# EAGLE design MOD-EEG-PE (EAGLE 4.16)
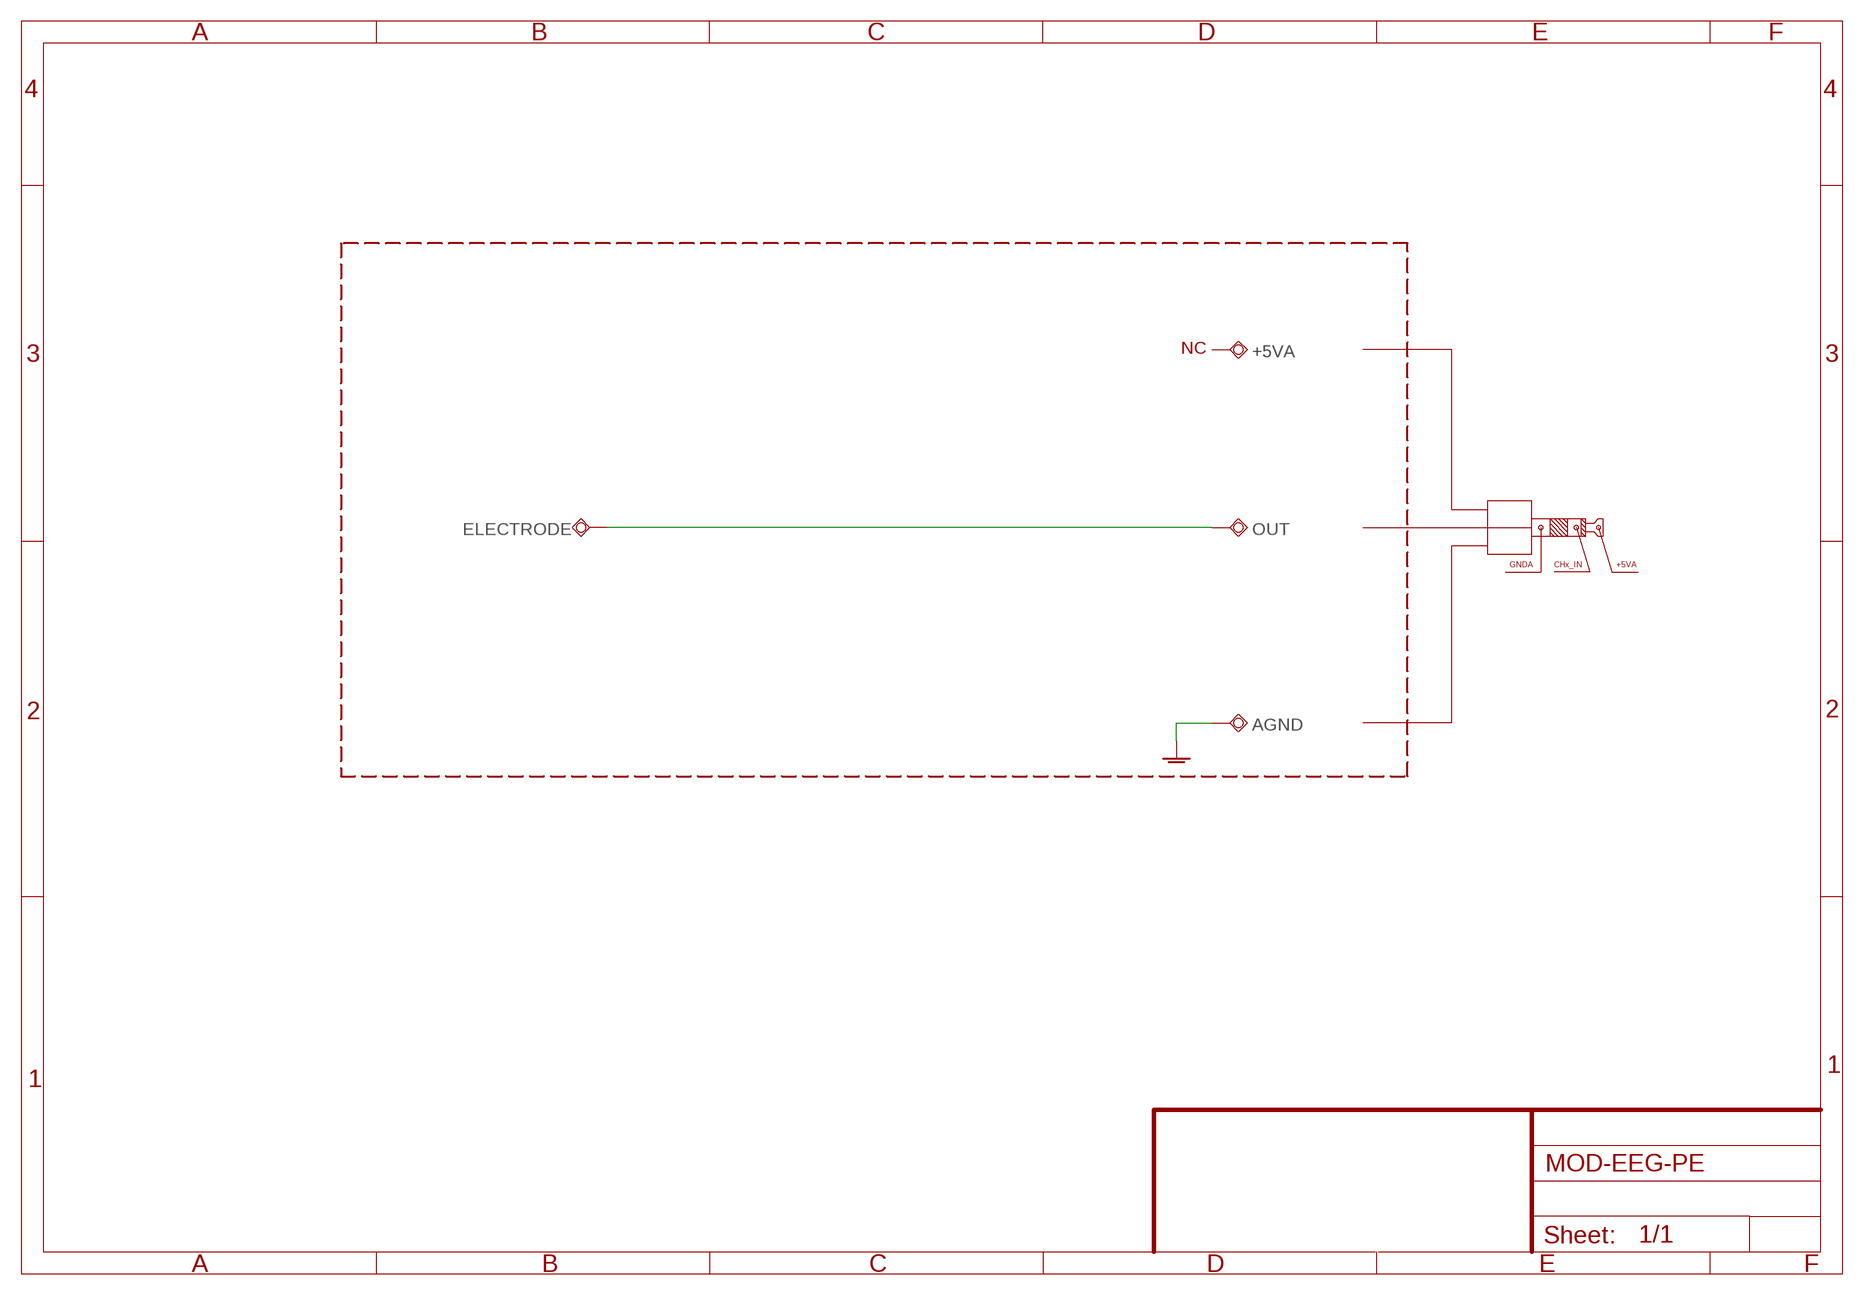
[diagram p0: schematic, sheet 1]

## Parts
+5VA  TESTPAD80/50  [SMD80/50]
AGND  TESTPAD80/50  [SMD80/50]
ELECTRODE  TESTPAD80/50  [SMD80/50]
OUT  TESTPAD80/50  [SMD80/50]

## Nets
ELECTRODE: ELECTRODE.P$1(PP) OUT.P$1(PP)
GNDA: AGND.P$1(PP)
Unconnected: +5VA.P$1(PP)

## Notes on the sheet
- NC
- GNDA | CHx_IN | +5VA

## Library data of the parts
+5VA AGND ELECTRODE OUT = gogo:TESTPAD: drill 40mils, diameter 70mils

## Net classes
1 pwr: width 0.4 mm, drill 0.23 mm

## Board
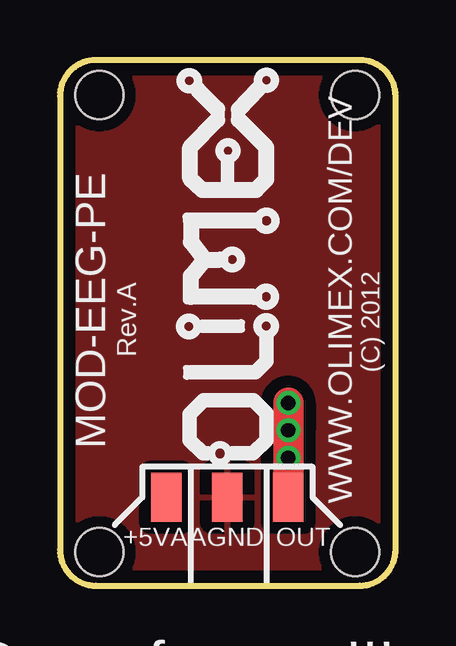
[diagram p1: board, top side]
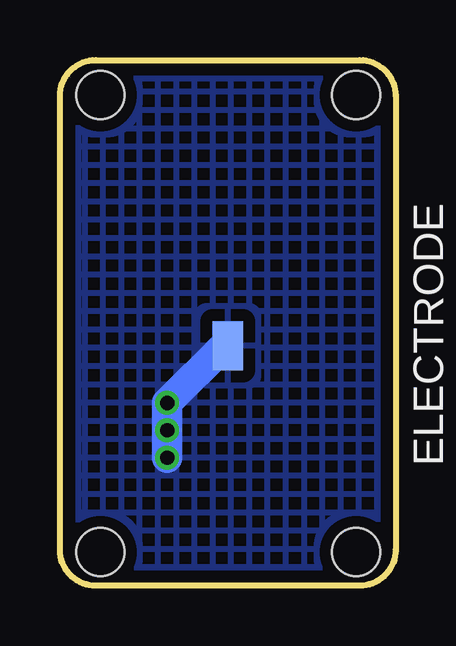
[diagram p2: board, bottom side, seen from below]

Size 14 x 21.91 mm. Coordinates in mm from the lower left corner, seen from the top.
Outline: 12.5,0 arc90 14,1.5 14,20.41 arc90 12.5,21.91 1.5,21.91 arc90 0,20.41 0,1.5 arc90 1.5,0 12.5,0
Copper layers (1+16): Top 0.035mm / dielectric 1.5mm / Bottom 0.035mm
Design rules "default": minimum track width 10mil, minimum drill 0.6mm, track to track 10mil, track to pad 10mil, pad to pad 10mil, via to via 10mil, smd to smd 1mil, copper to edge 10mil, drill to drill 10mil, minimum pad ring 10mil, minimum via ring 8mil, stop-mask expansion 4mil, vias tented up to drill 28mil, thermal gap 20mil
Holes 2 mm at 1.65,1.4 12.32,1.4 1.65,20.45 12.32,20.45

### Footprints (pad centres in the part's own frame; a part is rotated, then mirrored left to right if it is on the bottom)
SMD80/50 = smd 2.032 x 1.27: P$1 0,0

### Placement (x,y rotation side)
+5VA  4.45,3.68 90 top
AGND  6.99,3.68 90 top
ELECTRODE  7,10 270 bottom
OUT  9.53,3.68 90 top
U$1  [OLIMEX1_V]  9.27,22.73 90 top

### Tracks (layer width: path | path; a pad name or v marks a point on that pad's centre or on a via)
ELECTRODE  (via drill 0.6)
  Top 1.27: OUT.P$1 v9.53,5.33 v9.53,6.48 v9.53,7.62
  Bottom 1.27: v9.53,5.33 v9.53,7.62 7.14,10 ELECTRODE.P$1
  pour Bottom (isolate 0.508, hatched): 0,20.41 arc-90 1.5,21.91 12.5,21.91 arc-90 14,20.41 14,1.5 arc-90 12.5,0 1.5,0 arc-90 0,1.5
GNDA
  pour Top (isolate 0.508): 0,20.41 arc-90 1.5,21.91 12.5,21.91 arc-90 14,20.41 14,1.5 arc-90 12.5,0 1.5,0 arc-90 0,1.5

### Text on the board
tNames: Rev.A | (C) 2012 | MOD-EEG-PE | WWW.OLIMEX.COM/DEV | Da se frezova!!!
